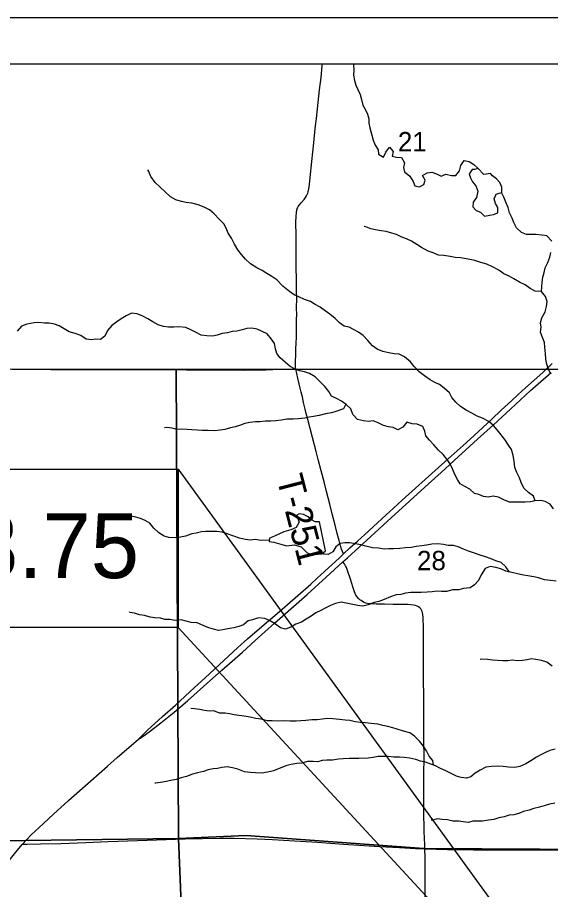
# Model space of a CAD drawing. Extents: x 0 to 34, y 0 to 22.
# Drawn here: x 13.115 to 14.264, y 14.196 to 16.078 of the extents above; entities that cross this region are included whole.
import ezdxf

# ---------------------------------------------------------------- set-up
doc = ezdxf.new("R2010")
doc.units = 0
for name, color, linetype in [('GM_X_Minor_Lake', 7, 'Continuous'), ('GM_X_Minor_River', 7, 'Continuous'), ('GM_X_Section', 7, 'Continuous'), ('GM_X_Section_Text', 7, 'Continuous'), ('GM_X_State_Route', 7, 'Continuous'), ('GM_X_Township_Road', 7, 'Continuous'), ('GM_X_Township_Road_Text', 7, 'Continuous'), ('GM_X_US_Route', 7, 'Continuous'), ('SH_Data', 7, 'Continuous'), ('SH_Text', 7, 'Continuous')]:
    doc.layers.add(name, color=color, linetype=linetype)

msp = doc.modelspace()

# ---------------------------------------------------------------- linework, layer by layer
at = {"layer": 'GM_X_Minor_Lake'}
for points in [[(14.1085, 15.7517), (14.1002, 15.7495), (14.0949, 15.7495), (14.0922, 15.745), (14.0888, 15.7394), (14.0917, 15.7314), (14.0962, 15.723), (14.1029, 15.7142), (14.1074, 15.7028), (14.1046, 15.6888), (14.0977, 15.679), (14.0969, 15.6691), (14.104, 15.6607), (14.1134, 15.6572), (14.1221, 15.6491), (14.1334, 15.6513), (14.1414, 15.6524), (14.1505, 15.6557), (14.1502, 15.6674), (14.1458, 15.6758), (14.1428, 15.6865), (14.1467, 15.6959), (14.1535, 15.6981), (14.1592, 15.6996), (14.1589, 15.7117), (14.1545, 15.7216), (14.1474, 15.7293), (14.1387, 15.7358), (14.1346, 15.7408), (14.1206, 15.7387)], [(14.1206, 15.7387), (14.1085, 15.7517)], [(13.7662, 14.9894), (13.7571, 14.9891), (13.7507, 14.9926), (13.742, 14.9999), (13.7318, 15.0053), (13.7224, 15.0065), (13.7171, 15.0039), (13.7185, 14.9978), (13.7222, 14.9887), (13.7161, 14.9774), (13.7047, 14.9718), (13.6895, 14.9678), (13.6693, 14.9581), (13.6587, 14.9544), (13.6579, 14.9468), (13.6677, 14.9456), (13.6828, 14.9409), (13.6953, 14.9374), (13.712, 14.9399), (13.7267, 14.9352), (13.7395, 14.9221), (13.7508, 14.9178), (13.7629, 14.9196), (13.7709, 14.9203), (13.7789, 14.9271)], [(13.7789, 14.9271), (13.7662, 14.9894)]]:
    msp.add_lwpolyline(points, dxfattribs=at)
at = {"layer": 'GM_X_Minor_River'}
for points in [[(13.8393, 15.9775), (13.8397, 15.9747), (13.8404, 15.9637), (13.8395, 15.9531), (13.8417, 15.9417), (13.8446, 15.9314), (13.8491, 15.9219), (13.8536, 15.9116), (13.8569, 15.9006), (13.8594, 15.8884), (13.865, 15.8785), (13.8695, 15.869), (13.8724, 15.8591), (13.8727, 15.8492), (13.8749, 15.8393), (13.8793, 15.8233), (13.8819, 15.8131), (13.8863, 15.802), (13.8927, 15.7921), (13.8933, 15.7822), (13.9039, 15.7764), (13.9093, 15.787), (13.9173, 15.7976), (13.9248, 15.788), (13.9225, 15.7782), (13.9323, 15.7758), (13.9429, 15.7757), (13.9496, 15.7642), (13.9473, 15.754), (13.9491, 15.7441), (13.9611, 15.7353), (13.9678, 15.7238), (13.9715, 15.7139), (13.9817, 15.7119), (13.9912, 15.7168), (13.994, 15.7266), (13.988, 15.7362), (13.9979, 15.7421)], [(13.9979, 15.7421), (14.0081, 15.7436), (14.0183, 15.7404), (14.0281, 15.7354), (14.0384, 15.7391), (14.0505, 15.7367), (14.0603, 15.7362), (14.068, 15.7464), (14.0711, 15.7581), (14.078, 15.7691), (14.089, 15.7667), (14.0988, 15.7601), (14.1082, 15.7516)], [(14.2312, 15.0346), (14.2275, 15.0445), (14.2166, 15.0529), (14.2064, 15.0621), (14.2008, 15.0743), (14.1972, 15.0846), (14.1916, 15.0961), (14.1871, 15.1063), (14.1857, 15.12), (14.1835, 15.1322), (14.1802, 15.1451), (14.1735, 15.155), (14.1653, 15.1669), (14.1522, 15.1845), (14.1417, 15.1967), (14.1308, 15.2055), (14.1176, 15.2132), (14.1063, 15.2175), (14.0942, 15.2241), (14.0821, 15.2303), (14.0701, 15.2384), (14.0599, 15.2472), (14.0513, 15.2575), (14.0461, 15.2674), (14.0352, 15.2778), (14.0247, 15.2855), (14.0145, 15.2901), (14.0047, 15.2955), (13.9923, 15.304), (13.981, 15.3132), (13.9705, 15.3247), (13.9622, 15.3343), (13.9495, 15.3454), (13.9381, 15.3508), (13.9272, 15.3517), (13.9154, 15.3537), (13.9026, 15.3565), (13.8905, 15.3615), (13.8804, 15.3688), (13.8702, 15.3803), (13.8605, 15.3914), (13.8499, 15.3983), (13.8398, 15.4041), (13.83, 15.4092), (13.8194, 15.4112), (13.8092, 15.4185), (13.8002, 15.428), (13.7882, 15.4376), (13.7784, 15.4449), (13.7678, 15.4523), (13.7569, 15.4584), (13.7467, 15.4646), (13.7335, 15.4693), (13.7215, 15.4751), (13.7116, 15.4794), (13.7015, 15.4859), (13.6868, 15.4978), (13.6744, 15.5116), (13.6631, 15.5185), (13.653, 15.5251), (13.6428, 15.5316), (13.6311, 15.537), (13.6175, 15.5459), (13.607, 15.5559), (13.598, 15.5662), (13.5902, 15.5765), (13.5831, 15.5884), (13.5764, 15.6013), (13.5693, 15.612), (13.5648, 15.6227), (13.5603, 15.6322), (13.5498, 15.6426), (13.5389, 15.654), (13.5288, 15.6621), (13.5179, 15.6679), (13.5047, 15.6733), (13.4907, 15.6765), (13.4789, 15.6781), (13.4684, 15.6805), (13.4567, 15.6841), (13.4453, 15.6906), (13.4337, 15.701), (13.4228, 15.7117), (13.4119, 15.7217), (13.4026, 15.7343), (13.3985, 15.7449), (13.3962, 15.7488)], [(14.2666, 15.5946), (14.2561, 15.6065), (14.2455, 15.6081), (14.2331, 15.6093), (14.2232, 15.6091), (14.2126, 15.6095), (14.2013, 15.6135), (14.1911, 15.6234), (14.1852, 15.6349), (14.1815, 15.6444), (14.1755, 15.6562), (14.1726, 15.6672), (14.1678, 15.6787), (14.1633, 15.6897), (14.1588, 15.6995)], [(14.2449, 15.4866), (14.2313, 15.4872), (14.2203, 15.493), (14.2098, 15.5007), (14.1973, 15.5061), (14.1853, 15.5138), (14.1747, 15.5192), (14.1634, 15.5243), (14.1525, 15.5324), (14.1393, 15.5393), (14.1265, 15.5451), (14.114, 15.549), (14.1008, 15.553), (14.0902, 15.5553), (14.0705, 15.5586), (14.0584, 15.5598), (14.0475, 15.5615), (14.0342, 15.5639), (14.0229, 15.5647), (14.0108, 15.5694), (14.0002, 15.5733), (13.9863, 15.5814), (13.9761, 15.5876), (13.9648, 15.5949), (13.9535, 15.5999), (13.9433, 15.6038), (13.9324, 15.6092), (13.9222, 15.6124), (13.9097, 15.6155), (13.8991, 15.6168), (13.887, 15.6192), (13.8768, 15.6212), (13.8659, 15.6258), (13.8621, 15.6262)], [(14.2649, 15.3082), (14.2594, 15.3189), (14.2553, 15.3314), (14.2539, 15.3409), (14.2532, 15.3515), (14.2522, 15.3664), (14.2508, 15.3762), (14.2467, 15.3873), (14.2422, 15.3983), (14.2438, 15.4093), (14.2428, 15.4188), (14.2451, 15.4294), (14.2525, 15.4426), (14.2556, 15.4536), (14.2568, 15.4646), (14.2531, 15.4752), (14.2449, 15.4859), (14.2453, 15.4965), (14.2462, 15.5064), (14.2474, 15.517), (14.2505, 15.5272), (14.2529, 15.5371), (14.2583, 15.5488), (14.2629, 15.5605), (14.2649, 15.5707)], [(13.6092, 15.4064), (13.5997, 15.4034), (13.5883, 15.4009), (13.5777, 15.3999), (13.5678, 15.3969), (13.5561, 15.3959), (13.5454, 15.3922), (13.5356, 15.39), (13.5235, 15.3909), (13.511, 15.3922), (13.5004, 15.3976), (13.4887, 15.4034), (13.4782, 15.4084), (13.463, 15.4101), (13.452, 15.4094), (13.4407, 15.4095), (13.4301, 15.4108), (13.4184, 15.4143), (13.4067, 15.4209), (13.3961, 15.4274), (13.3852, 15.4328), (13.3735, 15.4379), (13.361, 15.4395), (13.3496, 15.4339), (13.339, 15.4276), (13.3294, 15.4209), (13.3184, 15.413), (13.3092, 15.4021), (13.3038, 15.3896), (13.2943, 15.3825), (13.2844, 15.3837), (13.2746, 15.3819), (13.2632, 15.3836), (13.2516, 15.3913), (13.2395, 15.3956), (13.2266, 15.3995), (13.2157, 15.406), (13.2048, 15.4122), (13.195, 15.4157), (13.1836, 15.4181), (13.1734, 15.4182), (13.1609, 15.4195), (13.1514, 15.4184), (13.1355, 15.4155), (13.1237, 15.4115), (13.1146, 15.4006)], [(14.2708, 15.0175), (14.2633, 15.0271), (14.2528, 15.0332), (14.2429, 15.0352), (14.2312, 15.0346), (14.2206, 15.0324), (14.2096, 15.0321), (14.1978, 15.0315), (14.1755, 15.0317), (14.1634, 15.0368), (14.1521, 15.0429), (14.1404, 15.0449), (14.1298, 15.0424), (14.1199, 15.044), (14.1097, 15.0483), (14.0999, 15.0507), (14.0902, 15.0595), (14.0796, 15.0656), (14.0694, 15.0714), (14.0634, 15.081), (14.0575, 15.0913), (14.053, 15.1035), (14.0475, 15.1145), (14.0403, 15.1248), (14.0325, 15.1348), (14.0227, 15.1436), (14.0126, 15.1555), (14.0036, 15.1654), (13.995, 15.175), (13.9935, 15.1849), (13.9891, 15.1948), (13.9766, 15.1998), (13.966, 15.2011), (13.9547, 15.2046), (13.9455, 15.1937), (13.9352, 15.1881), (13.925, 15.1927), (13.9148, 15.194), (13.9039, 15.1975), (13.8929, 15.2029), (13.882, 15.2072), (13.8718, 15.2058), (13.8608, 15.2074), (13.8483, 15.2102), (13.8378, 15.2209), (13.8334, 15.2331), (13.824, 15.2427), (13.8134, 15.2496), (13.8025, 15.2554), (13.7923, 15.2604), (13.786, 15.2707), (13.7777, 15.2811), (13.7567, 15.3025), (13.7447, 15.3094), (13.7337, 15.313), (13.7231, 15.315), (13.7126, 15.3196), (13.7028, 15.3243), (13.6926, 15.3331), (13.6817, 15.3431), (13.6742, 15.3526), (13.6716, 15.3625), (13.6695, 15.3739), (13.6627, 15.3835), (13.6537, 15.3946), (13.6424, 15.4), (13.6315, 15.405), (13.6205, 15.4074), (13.6092, 15.4064)], [(13.8226, 15.2435), (13.8179, 15.2332), (13.8011, 15.2277), (13.7917, 15.2248), (13.7791, 15.2226), (13.7651, 15.2186), (13.7533, 15.2164), (13.7439, 15.215), (13.7344, 15.2128), (13.7203, 15.2118), (13.7097, 15.2108), (13.6957, 15.2105), (13.6843, 15.2087), (13.6722, 15.207), (13.6612, 15.2067), (13.6499, 15.2064), (13.6377, 15.2054), (13.6279, 15.2051), (13.6161, 15.2037), (13.6055, 15.2012), (13.5957, 15.1982), (13.5843, 15.1945), (13.574, 15.1924), (13.5619, 15.1883), (13.552, 15.1869), (13.5395, 15.1855), (13.5263, 15.1864), (13.513, 15.1861), (13.5032, 15.187), (13.491, 15.1875), (13.4808, 15.1883), (13.4691, 15.1892), (13.4589, 15.1885), (13.4487, 15.1913), (13.4373, 15.1925), (13.4324, 15.1918)], [(13.6582, 14.9495), (13.6397, 14.9493), (13.6284, 14.9509), (13.6166, 14.9495), (13.6064, 14.9515), (13.594, 14.9543), (13.5792, 14.959), (13.5671, 14.9633), (13.5562, 14.9672), (13.5448, 14.9688), (13.5335, 14.9685), (13.5214, 14.9686), (13.5119, 14.9676), (13.5005, 14.9651), (13.4907, 14.9636), (13.4774, 14.9581), (13.4667, 14.9563), (13.4554, 14.9545), (13.4417, 14.9558), (13.4315, 14.9585), (13.4199, 14.9658), (13.4093, 14.9758), (13.4007, 14.9861), (13.3905, 14.9923), (13.3807, 14.9962), (13.3702, 14.9997), (13.3596, 15.0017), (13.3599, 15.0009)], [(14.1755, 14.8809), (14.1675, 14.8922), (14.1577, 14.9014), (14.1464, 14.9053), (14.1362, 14.9095), (14.1241, 14.9135), (14.1124, 14.9174), (14.0984, 14.9221), (14.0871, 14.9263), (14.0762, 14.9302), (14.0652, 14.9353), (14.0547, 14.938), (14.0437, 14.9385), (14.0331, 14.9405), (14.021, 14.9418), (14.0081, 14.9411), (13.9971, 14.939), (13.9869, 14.9379), (13.9747, 14.9362), (13.9637, 14.934), (13.9512, 14.933), (13.9395, 14.9316), (13.9258, 14.9309), (13.9156, 14.931), (13.9058, 14.9304), (13.8933, 14.9328), (13.8804, 14.9333), (13.8661, 14.9368), (13.8551, 14.94), (13.843, 14.942), (13.8317, 14.944), (13.8211, 14.9437), (13.8108, 14.9423), (13.8013, 14.9356), (13.7952, 14.9246), (13.7845, 14.9187), (13.7756, 14.9196), (13.7727, 14.9219)], [(14.2763, 14.8611), (14.2638, 14.8624), (14.2513, 14.8644), (14.2385, 14.8687), (14.2279, 14.8707), (14.2154, 14.8727), (14.2056, 14.874), (14.1678, 14.8827), (14.1569, 14.8877), (14.1463, 14.8905), (14.1342, 14.8932), (14.1232, 14.8884), (14.1143, 14.8752), (14.1089, 14.8631), (14.1001, 14.8534), (14.0906, 14.8466), (14.0762, 14.8452), (14.0663, 14.8427), (14.0531, 14.8428), (14.0409, 14.8391), (14.0288, 14.8393), (14.0186, 14.8397), (14.0087, 14.8383), (13.9981, 14.8373), (13.9853, 14.837), (13.975, 14.8371), (13.9629, 14.8369), (13.9512, 14.8351), (13.9413, 14.8329), (13.9314, 14.8319), (13.9189, 14.8278), (13.9052, 14.8215), (13.8942, 14.8178), (13.884, 14.8156), (13.8714, 14.8104), (13.8597, 14.8075), (13.8491, 14.8091), (13.8377, 14.8111), (13.8234, 14.8139), (13.8128, 14.8163), (13.8006, 14.813), (13.79, 14.8086), (13.7797, 14.8037), (13.7687, 14.7978), (13.7584, 14.7929), (13.7485, 14.7855), (13.7375, 14.7791), (13.7272, 14.7728), (13.7151, 14.7683), (13.7044, 14.7624), (13.693, 14.7575), (13.6824, 14.7607), (13.6689, 14.7699), (13.6583, 14.7768), (13.6481, 14.7807), (13.6349, 14.782), (13.622, 14.7776), (13.6125, 14.7754), (13.6022, 14.7668), (13.5923, 14.7638), (13.5813, 14.7609), (13.5688, 14.7584), (13.5578, 14.7566), (13.5483, 14.7552), (13.5374, 14.7579), (13.5276, 14.7607), (13.5155, 14.7657), (13.5023, 14.7712), (13.4898, 14.7724), (13.4788, 14.7752), (13.4679, 14.7776), (13.4546, 14.7762), (13.4436, 14.7786), (13.433, 14.7783), (13.4232, 14.7818), (13.4111, 14.7819), (13.4013, 14.7839), (13.3888, 14.7871), (13.3782, 14.7887), (13.3673, 14.7926), (13.3574, 14.7934), (13.3567, 14.795)], [(14.2675, 14.6776), (14.2559, 14.6864), (14.2449, 14.6903), (14.2328, 14.6923), (14.223, 14.6936), (14.2135, 14.6914), (14.204, 14.69), (14.1919, 14.6893), (14.1813, 14.6909), (14.1718, 14.6895), (14.1616, 14.6896), (14.1499, 14.6905), (14.1397, 14.691), (14.1283, 14.6922), (14.1158, 14.6927), (14.1128, 14.6924)], [(14.0119, 14.4642), (14.0102, 14.4741), (14.0023, 14.484), (13.9971, 14.4951), (13.9904, 14.5054), (13.9818, 14.5161), (13.9709, 14.5268), (13.9607, 14.5341), (13.9475, 14.538), (13.9339, 14.542), (13.9241, 14.5447), (13.9131, 14.5475), (13.9025, 14.5499), (13.8916, 14.5526), (13.8772, 14.5539), (13.8647, 14.5559), (13.8541, 14.5564), (13.8428, 14.5576), (13.8314, 14.5604), (13.8212, 14.5616), (13.8091, 14.5629), (13.7947, 14.5646), (13.7834, 14.5647), (13.772, 14.5636), (13.7614, 14.5622), (13.75, 14.562), (13.7368, 14.561), (13.7262, 14.5599), (13.7159, 14.5596), (13.7027, 14.5594), (13.6913, 14.5599), (13.6769, 14.5596), (13.6644, 14.5598), (13.6538, 14.5602), (13.6406, 14.5638), (13.6289, 14.565), (13.6168, 14.5678), (13.6039, 14.5702), (13.5926, 14.5718), (13.5824, 14.5727), (13.5725, 14.5751), (13.5627, 14.5767), (13.5506, 14.5768), (13.5381, 14.5815), (13.5283, 14.5808), (13.5181, 14.5824), (13.5083, 14.5844), (13.4965, 14.5857), (13.4886, 14.5865)], [(14.2743, 14.4992), (14.2626, 14.4959), (14.2531, 14.4918), (14.2432, 14.487), (14.2337, 14.4814), (14.2219, 14.4735), (14.2112, 14.4672), (14.1983, 14.4616), (14.1869, 14.4591), (14.1737, 14.4599), (14.1619, 14.4612), (14.1491, 14.4621), (14.1366, 14.4618), (14.1244, 14.4597), (14.1123, 14.4537), (14.102, 14.4474), (14.0925, 14.4395), (14.083, 14.4365), (14.0712, 14.4378), (14.0614, 14.4409), (14.0497, 14.4467), (14.0384, 14.4522), (14.0271, 14.4572), (14.0162, 14.4626), (14.006, 14.4665), (13.9946, 14.4708), (13.9837, 14.4728), (13.9739, 14.4767), (13.961, 14.4795), (13.9489, 14.4811), (13.9387, 14.4816), (13.9266, 14.4817), (13.9141, 14.483), (13.9024, 14.4831), (13.8925, 14.4832), (13.8819, 14.4806), (13.8713, 14.4796), (13.8512, 14.479), (13.8413, 14.4787), (13.8304, 14.4785), (13.8171, 14.4778), (13.8073, 14.4772), (13.794, 14.4754), (13.7822, 14.4751), (13.772, 14.4745), (13.7625, 14.4715), (13.7527, 14.472), (13.7402, 14.4721), (13.7284, 14.4685), (13.717, 14.4678), (13.7049, 14.4656), (13.6939, 14.4627), (13.6673, 14.4524), (13.6544, 14.4491), (13.6419, 14.4473), (13.6283, 14.4478), (13.6173, 14.4487), (13.6048, 14.4503), (13.5901, 14.4554), (13.5784, 14.4585), (13.5674, 14.4605), (13.556, 14.4595), (13.5462, 14.4573), (13.5367, 14.4563), (13.5265, 14.4545), (13.5158, 14.4508), (13.5033, 14.4475), (13.4927, 14.4446), (13.4794, 14.4401), (13.468, 14.4368), (13.457, 14.4335), (13.4456, 14.4314), (13.4357, 14.4288), (13.4232, 14.427)], [(13.4232, 14.427), (13.4137, 14.4256), (13.4115, 14.4256)], [(14.2737, 14.3827), (14.2616, 14.3805), (14.2502, 14.3769), (14.2407, 14.3739), (14.2282, 14.371), (14.2179, 14.3673), (14.2062, 14.3644), (14.1959, 14.3603), (14.1849, 14.3574), (14.1747, 14.3564), (14.1644, 14.353), (14.1527, 14.3505), (14.142, 14.3472), (14.1307, 14.3454), (14.1174, 14.3432), (14.1072, 14.3433), (14.0969, 14.3434), (14.0875, 14.3409), (14.0761, 14.3421), (14.0659, 14.3438), (14.0538, 14.3435), (14.0417, 14.3463), (14.0307, 14.3471), (14.0205, 14.3487), (14.0099, 14.3454), (14.0072, 14.3455)]]:
    msp.add_lwpolyline(points, dxfattribs=at)
at = {"layer": 'GM_X_Section'}
for points in [[(13.4573, 15.3188), (13.4623, 14.3061), (12.9117, 14.2993), (12.486, 14.3129), (12.4684, 15.3203)], [(14.4882, 15.3186), (14.4911, 14.2816), (13.9911, 14.2848), (13.6079, 14.3123), (13.4623, 14.3061), (13.4573, 15.3188)], [(13.4623, 14.3061), (13.5034, 13.3022), (12.5967, 13.3052), (12.4929, 13.3075), (12.486, 14.3129), (12.9117, 14.2993)], [(14.4911, 14.2816), (14.5077, 13.2997), (13.5746, 13.3006), (13.5034, 13.3022), (13.4623, 14.3061), (13.6079, 14.3123), (13.9911, 14.2848)]]:
    msp.add_lwpolyline(points, close=True, dxfattribs=at)
at = {"layer": 'GM_X_State_Route'}
msp.add_lwpolyline([(13.1257, 14.2936), (13.1361, 14.2939), (13.1649, 14.2946), (13.2084, 14.2957), (13.2624, 14.2974), (13.3099, 14.2994), (13.3741, 14.302), (13.4766, 14.3054), (13.5139, 14.3064), (13.5511, 14.3071), (13.5822, 14.3071), (13.6318, 14.3057), (13.6647, 14.3042), (13.7126, 14.3013), (13.762, 14.2979), (13.8178, 14.2942), (13.8954, 14.2891), (13.9388, 14.2866), (13.973, 14.2849), (13.9934, 14.2841), (14.0418, 14.2827), (14.098, 14.2818), (14.1581, 14.2818), (14.2231, 14.282), (14.2886, 14.2816)], dxfattribs=at)
at = {"layer": 'GM_X_Township_Road'}
for points in [[(13.715, 15.3185), (13.7145, 15.3227), (13.7144, 15.3281), (13.7144, 15.3328), (13.7145, 15.3367), (13.7146, 15.3402), (13.7148, 15.3448), (13.7152, 15.3579), (13.7154, 15.3641), (13.7155, 15.3672), (13.7156, 15.3703), (13.7163, 15.392), (13.7165, 15.4049), (13.7168, 15.4153), (13.7169, 15.4274), (13.7172, 15.4355), (13.7169, 15.4521), (13.717, 15.47), (13.7168, 15.4882), (13.7165, 15.5071), (13.716, 15.5437), (13.716, 15.5632), (13.7159, 15.586), (13.7156, 15.6073), (13.7155, 15.6352), (13.7158, 15.6485), (13.7164, 15.6563), (13.7175, 15.6625), (13.7188, 15.6666), (13.7204, 15.6693), (13.7231, 15.673), (13.7263, 15.6773), (13.7331, 15.6849), (13.7361, 15.6892), (13.738, 15.6928), (13.7397, 15.6956), (13.7408, 15.6986), (13.7418, 15.7012), (13.7433, 15.7074), (13.7444, 15.717), (13.7461, 15.7324), (13.7495, 15.7666), (13.7537, 15.8071), (13.7554, 15.8228), (13.7576, 15.8437), (13.7595, 15.8595), (13.7621, 15.8807), (13.7665, 15.921), (13.7695, 15.9477), (13.7722, 15.9732), (13.7727, 15.9775)], [(13.1032, 15.3187), (13.1312, 15.3184), (13.1872, 15.318), (13.2307, 15.3181), (13.2618, 15.3181), (13.3395, 15.318), (13.3985, 15.3177), (13.4265, 15.3179), (13.442, 15.318), (13.4793, 15.3176), (13.5663, 15.3171), (13.6036, 15.3167), (13.6378, 15.3173), (13.6502, 15.3176), (13.6657, 15.3181), (13.6873, 15.3186), (13.6998, 15.3185), (13.7091, 15.3185), (13.715, 15.3185)], [(13.8182, 14.9205), (13.8154, 14.9254), (13.8135, 14.9304), (13.8113, 14.9377), (13.8083, 14.9494), (13.8045, 14.9643), (13.7999, 14.9821), (13.7933, 15.0067), (13.7882, 15.0275), (13.7813, 15.0546), (13.776, 15.0756), (13.7696, 15.0993), (13.7632, 15.1238), (13.7588, 15.1412), (13.7512, 15.1713), (13.7408, 15.2103), (13.7376, 15.2234), (13.7352, 15.2324), (13.7319, 15.2468), (13.7292, 15.2587), (13.7267, 15.269), (13.7246, 15.278), (13.7224, 15.287), (13.7198, 15.299), (13.717, 15.3097), (13.715, 15.3185)], [(13.9934, 14.2841), (13.993, 14.2921), (13.9922, 14.3079), (13.9919, 14.3203), (13.9917, 14.3366), (13.9912, 14.3514), (13.991, 14.3819), (13.9911, 14.3915), (13.9908, 14.4102), (13.9912, 14.4258), (13.9913, 14.4471), (13.9915, 14.4784), (13.9915, 14.4937), (13.9912, 14.5064), (13.9912, 14.5279), (13.9914, 14.5428), (13.9913, 14.5614), (13.9913, 14.5768), (13.9911, 14.5956), (13.9909, 14.6128), (13.9911, 14.6226), (13.9905, 14.6388), (13.9906, 14.6633), (13.9905, 14.6791), (13.9905, 14.6926), (13.9904, 14.707), (13.9905, 14.728), (13.9901, 14.7406), (13.9904, 14.7598), (13.9895, 14.7828), (13.9891, 14.7895), (13.9884, 14.793), (13.9874, 14.7959), (13.9862, 14.7985), (13.9846, 14.8013), (13.9826, 14.8036), (13.9798, 14.8057), (13.9768, 14.8074), (13.9731, 14.8088), (13.9687, 14.8099), (13.9563, 14.8108), (13.9408, 14.811), (13.9246, 14.8112), (13.9064, 14.8115), (13.888, 14.8119), (13.8784, 14.8124), (13.8723, 14.8127), (13.8659, 14.814), (13.8622, 14.8156), (13.8587, 14.8174), (13.8557, 14.8193), (13.8532, 14.8211), (13.8501, 14.824), (13.8473, 14.8277), (13.8448, 14.8314), (13.8432, 14.8347), (13.8419, 14.838), (13.8383, 14.8488), (13.8334, 14.8635), (13.8267, 14.8842), (13.8242, 14.8907), (13.8223, 14.8946), (13.8198, 14.8985), (13.8167, 14.9029)], [(13.9938, 14.1617), (13.9938, 14.2022), (13.9936, 14.2277), (13.9936, 14.2641), (13.9934, 14.2841)]]:
    msp.add_lwpolyline(points, dxfattribs=at)
at = {"layer": 'GM_X_US_Route'}
for points in [[(13.3753, 14.5198), (13.3952, 14.5398), (13.4278, 14.5691), (13.4555, 14.5941), (13.4971, 14.6316), (13.5199, 14.6526), (13.5905, 14.7182), (13.6112, 14.7369), (13.6371, 14.7592), (13.6559, 14.7755), (13.6746, 14.7918), (13.7194, 14.8303), (13.7475, 14.8548), (13.7613, 14.8675), (13.777, 14.8825), (13.809, 14.9119), (13.8182, 14.9205), (13.8319, 14.9329), (13.8479, 14.9475), (13.8639, 14.9623), (13.8914, 14.9875), (13.9097, 15.0043), (13.9257, 15.019), (13.9441, 15.0358), (14.0226, 15.1063), (14.0502, 15.1313), (14.0756, 15.1542), (14.0985, 15.1752), (14.1374, 15.211), (14.1579, 15.2301), (14.1805, 15.2514), (14.1941, 15.2641), (14.2103, 15.2786), (14.2472, 15.3118), (14.2679, 15.3307)], [(13.3753, 14.5198), (13.3914, 14.5305), (13.4018, 14.5382), (13.4241, 14.5557), (13.4532, 14.5788), (13.4817, 14.6028), (13.4956, 14.6152), (13.5163, 14.634), (13.5559, 14.669), (13.6, 14.7083), (13.6278, 14.7331), (13.6695, 14.7704), (13.7393, 14.8323), (13.7806, 14.87), (13.8167, 14.9029), (13.8266, 14.9118), (13.8771, 14.9579), (13.9208, 14.9976), (14.001, 15.0711), (14.0286, 15.0961), (14.0652, 15.1299), (14.1065, 15.1675), (14.141, 15.1989), (14.1778, 15.2324), (14.2213, 15.2724), (14.2653, 15.3118)], [(13.1257, 14.2936), (13.1343, 14.3034), (13.1452, 14.3145), (13.1609, 14.3295), (13.1931, 14.3588), (13.2255, 14.3878), (13.2556, 14.4147), (13.3089, 14.4623), (13.33, 14.4807), (13.3558, 14.5031), (13.3753, 14.5198)], [(13.0601, 14.2114), (13.0914, 14.2512), (13.1148, 14.2805), (13.1257, 14.2936)]]:
    msp.add_lwpolyline(points, dxfattribs=at)
at = {"layer": 'SH_Data'}
for p, q in [((9.0079, 16.0775), (16.0079, 16.0775)), ((9.1079, 15.9775), (15.9079, 15.9775))]:
    msp.add_line(p, q, dxfattribs=at)
at = {"layer": 'SH_Text'}
for points in [[(12.1381, 15.1029), (13.4612, 15.1029), (13.4612, 14.7614), (12.1381, 14.7614)], [(13.4612, 15.1029), (14.6168, 13.5087), (13.4612, 14.7614)]]:
    msp.add_lwpolyline(points, close=True, dxfattribs=at)

# ---------------------------------------------------------------- texts
at = {"layer": 'GM_X_Section_Text'}
for s, p in [('21', (13.9351, 15.7885)), ('28', (13.9763, 14.8849))]:
    msp.add_text(s, height=0.04186, rotation=0, dxfattribs=at).set_placement(p)
at = {"layer": 'GM_X_Township_Road_Text'}
msp.add_text('T-251', height=0.05682, rotation=284.4403, dxfattribs=at).set_placement((13.6733, 15.0838))
at = {"layer": 'SH_Text'}
msp.add_text('ASD-71-13.75', height=0.14, dxfattribs=at).set_placement((12.1909, 14.8679))

doc.saveas('drawing.dxf')
